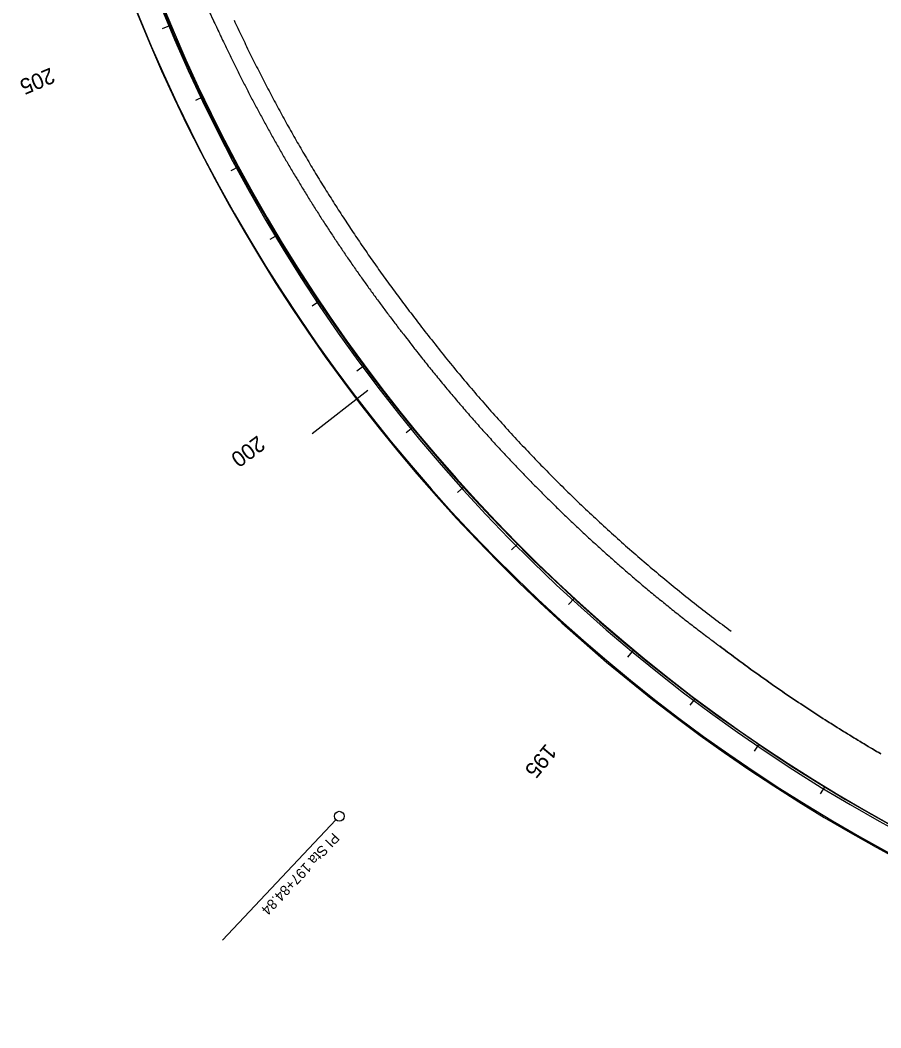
# Model space of a CAD drawing. Extents: x 5180909 to 5237144, y 3695282 to 3720102.
# Drawn here: x 5197859 to 5198956, y 3702771 to 3704056 of the extents above; entities that cross this region are included whole.
import ezdxf

# ---------------------------------------------------------------- set-up
doc = ezdxf.new("R2010")
doc.units = 0
for name, color, linetype in [('Alignment', 7, 'Continuous'), ('Default', 7, 'Continuous'), ('DisFieldPoint', 7, 'Continuous'), ('Draft_0', 7, 'Continuous'), ('dsnEntrancePaved', 7, 'Continuous'), ('dsnShadingGranular', 7, 'Continuous'), ('dsnSidewalkShadingRamp', 7, 'Continuous'), ('dsnStgShadingPropGrdLim', 7, 'Continuous')]:
    doc.layers.add(name, color=color, linetype=linetype)

msp = doc.modelspace()

# ---------------------------------------------------------------- linework, layer by layer
at = {"layer": 'Alignment'}
msp.add_arc((5199969.8, 3704853.2), 2080, 193.5037, 260.0302, dxfattribs=at)
at = {"layer": 'Default'}
msp.add_arc((5199969.8, 3704853.2), 2080, 193.5037, 260.0302, dxfattribs=at)
at = {"layer": 'DisFieldPoint'}
for radius in [2115.5, 2083.5]:
    msp.add_arc((5199970.6, 3704856.4), radius, 191.1921, 260.0343, dxfattribs=at)
at = {"layer": 'Draft_0'}
msp.add_line((5198231.3, 3703528.9), (5198302.4, 3703584.1), dxfattribs=at)
at = {"layer": 'dsnEntrancePaved'}
msp.add_arc((5199969.8, 3704853.2), 2080, 193.5037, 260.0302, dxfattribs=at)
at = {"layer": 'dsnShadingGranular'}
msp.add_line((5198110.1, 3704045.4), (5198110.1, 3704045.4), dxfattribs=at)
msp.add_line((5198110.1, 3704045.4), (5198110.1, 3704045.4), dxfattribs=at)
for centre, radius, start, end in [((5199967.6, 3704851), 2080, 188.6831, 264.8508), ((5199969.8, 3704853.2), 2114, 193.5037, 260.0302)]:
    msp.add_arc(centre, radius, start, end, dxfattribs=at)
for points in [[(5197987, 3704376.2), (5197987, 3704376.2), (5197988.6, 3704370.5), (5197991.8, 3704359.1), (5197996.7, 3704342.1), (5198001.8, 3704325.2), (5198007, 3704308.2), (5198012.4, 3704291.4), (5198017.9, 3704274.6), (5198023.6, 3704257.8), (5198029.4, 3704241.1), (5198035.3, 3704224.4), (5198041.4, 3704207.8), (5198047.7, 3704191.3), (5198054, 3704174.8), (5198060.6, 3704158.4), (5198067.2, 3704142), (5198074, 3704125.7), (5198081, 3704109.5), (5198088, 3704093.3), (5198095.3, 3704077.2), (5198102.6, 3704061.2), (5198107.6, 3704050.7), (5198110.1, 3704045.4), (5198110.1, 3704045.4)], [(5198110.1, 3704045.4), (5198113.3, 3704038.4), (5198116.6, 3704031.4), (5198119.9, 3704024.4), (5198123.3, 3704017.3), (5198126.7, 3704010.3), (5198130.1, 3704003.4), (5198133.5, 3703996.4), (5198137, 3703989.5), (5198140.5, 3703982.5), (5198144, 3703975.6), (5198147.6, 3703968.7), (5198151.1, 3703961.8), (5198154.7, 3703954.9), (5198158.3, 3703948.1), (5198162, 3703941.2), (5198165.7, 3703934.4), (5198169.4, 3703927.6), (5198173.1, 3703920.8), (5198176.8, 3703914), (5198180.6, 3703907.2), (5198184.4, 3703900.4), (5198188.3, 3703893.7), (5198192.1, 3703887), (5198196, 3703880.2), (5198199.9, 3703873.5), (5198203.8, 3703866.9), (5198207.8, 3703860.2), (5198211.8, 3703853.5), (5198215.8, 3703846.9), (5198219.8, 3703840.3), (5198223.8, 3703833.7), (5198227.9, 3703827.1), (5198232, 3703820.5), (5198236.2, 3703814), (5198240.3, 3703807.4), (5198244.5, 3703800.9), (5198248.7, 3703794.4), (5198252.9, 3703787.9), (5198257.2, 3703781.4), (5198261.5, 3703775), (5198265.8, 3703768.5), (5198270.1, 3703762.1), (5198274.4, 3703755.7), (5198278.8, 3703749.3), (5198283.2, 3703743), (5198287.6, 3703736.6), (5198292.1, 3703730.3), (5198296.6, 3703724), (5198301, 3703717.7), (5198305.6, 3703711.4), (5198310.1, 3703705.1), (5198314.7, 3703698.9), (5198319.3, 3703692.7), (5198323.9, 3703686.5), (5198328.5, 3703680.3), (5198333.2, 3703674.1), (5198337.9, 3703667.9), (5198342.6, 3703661.8), (5198347.3, 3703655.7), (5198352, 3703649.7)], [(5198352, 3703649.7), (5198357.6, 3703642.4), (5198363.3, 3703635), (5198369.2, 3703627.6), (5198375, 3703620.2), (5198380.9, 3703612.9), (5198386.8, 3703605.6), (5198392.7, 3703598.4), (5198398.6, 3703591.1), (5198404.7, 3703583.9), (5198410.7, 3703576.7), (5198416.7, 3703569.6), (5198422.8, 3703562.5), (5198428.9, 3703555.4), (5198435.1, 3703548.3), (5198441.3, 3703541.3), (5198447.5, 3703534.3), (5198453.8, 3703527.3), (5198460.1, 3703520.4), (5198466.4, 3703513.5), (5198472.7, 3703506.6), (5198479.1, 3703499.8), (5198485.5, 3703492.9), (5198492, 3703486.1), (5198498.5, 3703479.4), (5198505, 3703472.6), (5198511.5, 3703465.9), (5198518.1, 3703459.3), (5198524.7, 3703452.6), (5198531.3, 3703446), (5198538, 3703439.5), (5198544.6, 3703432.9), (5198551.4, 3703426.4), (5198558.1, 3703419.9), (5198564.9, 3703413.5), (5198571.7, 3703407.1), (5198578.6, 3703400.7), (5198585.4, 3703394.3), (5198592.3, 3703388), (5198599.2, 3703381.7), (5198606.2, 3703375.5), (5198613.2, 3703369.2), (5198620.2, 3703363.1), (5198627.2, 3703356.9), (5198634.3, 3703350.8), (5198641.4, 3703344.7), (5198648.5, 3703338.6), (5198655.6, 3703332.6), (5198662.8, 3703326.6), (5198670, 3703320.7), (5198677.3, 3703314.8), (5198684.5, 3703308.9), (5198691.8, 3703303), (5198699.1, 3703297.2), (5198706.5, 3703291.4), (5198713.8, 3703285.7), (5198721.2, 3703280), (5198728.7, 3703274.3), (5198736.1, 3703268.6), (5198743.6, 3703263.1), (5198751, 3703257.5)], [(5198751, 3703257.5), (5198754.2, 3703255), (5198760.8, 3703250.1), (5198770.7, 3703242.7), (5198780.6, 3703235.4), (5198790.6, 3703228.1), (5198800.7, 3703220.9), (5198810.7, 3703213.7), (5198820.8, 3703206.7), (5198831, 3703199.7), (5198841.2, 3703192.7), (5198851.4, 3703185.8), (5198861.7, 3703179), (5198872.1, 3703172.2), (5198882.4, 3703165.5), (5198892.8, 3703158.9), (5198903.3, 3703152.3), (5198913.8, 3703145.8), (5198924.3, 3703139.3), (5198934.9, 3703133), (5198945.5, 3703126.7), (5198952.6, 3703122.5), (5198956.2, 3703120.4)]]:
    msp.add_open_spline(points, degree=3, dxfattribs=at)
at = {"layer": 'dsnSidewalkShadingRamp'}
for p, q in [((5198051.5, 3704049), (5198040.2, 3704044.3)), ((5198092.4, 3703957.7), (5198082.5, 3703953)), ((5198137.6, 3703868.5), (5198127.9, 3703863.3)), ((5198187, 3703781.6), (5198177.6, 3703776)), ((5198240.6, 3703697.2), (5198231.5, 3703691.1)), ((5198298.2, 3703615.4), (5198288.3, 3703608.1)), ((5198359.6, 3703536.5), (5198351.1, 3703529.6)), ((5198424.7, 3703460.7), (5198416.6, 3703453.3)), ((5198493.4, 3703388), (5198485.6, 3703380.3)), ((5198565.6, 3703318.8), (5198558.1, 3703310.7)), ((5198640.9, 3703253.1), (5198633.1, 3703243.6)), ((5198719.4, 3703191), (5198712.7, 3703182.3)), ((5198800.7, 3703132.9), (5198794.5, 3703123.8)), ((5198884.7, 3703078.7), (5198879, 3703069.3)), ((5198261.6, 3703036.3), (5198117.3, 3702882.8))]:
    msp.add_line(p, q, dxfattribs=at)
msp.add_circle((5198265.9, 3703040.9), 6.25, dxfattribs=at)
for points in [[(5197987, 3704376.2), (5197987, 3704376.2), (5197988.6, 3704370.5), (5197991.8, 3704359.1), (5197996.7, 3704342.1), (5198001.8, 3704325.2), (5198007, 3704308.2), (5198012.4, 3704291.4), (5198017.9, 3704274.6), (5198023.6, 3704257.8), (5198029.4, 3704241.1), (5198035.3, 3704224.4), (5198041.4, 3704207.8), (5198047.7, 3704191.3), (5198054, 3704174.8), (5198060.6, 3704158.4), (5198067.2, 3704142), (5198074, 3704125.7), (5198081, 3704109.5), (5198088, 3704093.3), (5198095.3, 3704077.2), (5198102.6, 3704061.2), (5198107.6, 3704050.7), (5198110.1, 3704045.4), (5198110.1, 3704045.4)], [(5197987, 3704376.2), (5197987, 3704376.2), (5197988.6, 3704370.5), (5197991.8, 3704359.1), (5197996.7, 3704342.1), (5198001.8, 3704325.2), (5198007, 3704308.2), (5198012.4, 3704291.4), (5198017.9, 3704274.6), (5198023.6, 3704257.8), (5198029.4, 3704241.1), (5198035.3, 3704224.4), (5198041.4, 3704207.8), (5198047.7, 3704191.3), (5198054, 3704174.8), (5198060.6, 3704158.4), (5198067.2, 3704142), (5198074, 3704125.7), (5198081, 3704109.5), (5198088, 3704093.3), (5198095.3, 3704077.2), (5198102.6, 3704061.2), (5198107.6, 3704050.7), (5198110.1, 3704045.4), (5198110.1, 3704045.4)], [(5198110.1, 3704045.4), (5198113.3, 3704038.4), (5198116.6, 3704031.4), (5198119.9, 3704024.4), (5198123.3, 3704017.3), (5198126.7, 3704010.3), (5198130.1, 3704003.4), (5198133.5, 3703996.4), (5198137, 3703989.5), (5198140.5, 3703982.5), (5198144, 3703975.6), (5198147.6, 3703968.7), (5198151.1, 3703961.8), (5198154.7, 3703954.9), (5198158.3, 3703948.1), (5198162, 3703941.2), (5198165.7, 3703934.4), (5198169.4, 3703927.6), (5198173.1, 3703920.8), (5198176.8, 3703914), (5198180.6, 3703907.2), (5198184.4, 3703900.4), (5198188.3, 3703893.7), (5198192.1, 3703887), (5198196, 3703880.2), (5198199.9, 3703873.5), (5198203.8, 3703866.9), (5198207.8, 3703860.2), (5198211.8, 3703853.5), (5198215.8, 3703846.9), (5198219.8, 3703840.3), (5198223.8, 3703833.7), (5198227.9, 3703827.1), (5198232, 3703820.5), (5198236.2, 3703814), (5198240.3, 3703807.4), (5198244.5, 3703800.9), (5198248.7, 3703794.4), (5198252.9, 3703787.9), (5198257.2, 3703781.4), (5198261.5, 3703775), (5198265.8, 3703768.5), (5198270.1, 3703762.1), (5198274.4, 3703755.7), (5198278.8, 3703749.3), (5198283.2, 3703743), (5198287.6, 3703736.6), (5198292.1, 3703730.3), (5198296.6, 3703724), (5198301, 3703717.7), (5198305.6, 3703711.4), (5198310.1, 3703705.1), (5198314.7, 3703698.9), (5198319.3, 3703692.7), (5198323.9, 3703686.5), (5198328.5, 3703680.3), (5198333.2, 3703674.1), (5198337.9, 3703667.9), (5198342.6, 3703661.8), (5198347.3, 3703655.7), (5198352, 3703649.7)], [(5198110.1, 3704045.4), (5198113.3, 3704038.4), (5198116.6, 3704031.4), (5198119.9, 3704024.4), (5198123.3, 3704017.3), (5198126.7, 3704010.3), (5198130.1, 3704003.4), (5198133.5, 3703996.4), (5198137, 3703989.5), (5198140.5, 3703982.5), (5198144, 3703975.6), (5198147.6, 3703968.7), (5198151.1, 3703961.8), (5198154.7, 3703954.9), (5198158.3, 3703948.1), (5198162, 3703941.2), (5198165.7, 3703934.4), (5198169.4, 3703927.6), (5198173.1, 3703920.8), (5198176.8, 3703914), (5198180.6, 3703907.2), (5198184.4, 3703900.4), (5198188.3, 3703893.7), (5198192.1, 3703887), (5198196, 3703880.2), (5198199.9, 3703873.5), (5198203.8, 3703866.9), (5198207.8, 3703860.2), (5198211.8, 3703853.5), (5198215.8, 3703846.9), (5198219.8, 3703840.3), (5198223.8, 3703833.7), (5198227.9, 3703827.1), (5198232, 3703820.5), (5198236.2, 3703814), (5198240.3, 3703807.4), (5198244.5, 3703800.9), (5198248.7, 3703794.4), (5198252.9, 3703787.9), (5198257.2, 3703781.4), (5198261.5, 3703775), (5198265.8, 3703768.5), (5198270.1, 3703762.1), (5198274.4, 3703755.7), (5198278.8, 3703749.3), (5198283.2, 3703743), (5198287.6, 3703736.6), (5198292.1, 3703730.3), (5198296.6, 3703724), (5198301, 3703717.7), (5198305.6, 3703711.4), (5198310.1, 3703705.1), (5198314.7, 3703698.9), (5198319.3, 3703692.7), (5198323.9, 3703686.5), (5198328.5, 3703680.3), (5198333.2, 3703674.1), (5198337.9, 3703667.9), (5198342.6, 3703661.8), (5198347.3, 3703655.7), (5198352, 3703649.7)]]:
    msp.add_open_spline(points, degree=3, dxfattribs=at)
at = {"layer": 'dsnStgShadingPropGrdLim'}
for points in [[(5198131.8, 3704055.5), (5198135.1, 3704048.6), (5198141.6, 3704034.7), (5198151.6, 3704014), (5198161.9, 3703993.4), (5198172.4, 3703972.9), (5198183.1, 3703952.5), (5198194.1, 3703932.3), (5198205.3, 3703912.2), (5198216.7, 3703892.3), (5198228.4, 3703872.5), (5198240.2, 3703852.8), (5198252.3, 3703833.3), (5198264.7, 3703813.9), (5198277.2, 3703794.6), (5198289.9, 3703775.6), (5198302.9, 3703756.6), (5198316.1, 3703737.8), (5198329.5, 3703719.2), (5198343.1, 3703700.8), (5198356.9, 3703682.5), (5198366.3, 3703670.4), (5198370.9, 3703664.4)], [(5198370.9, 3703664.4), (5198376.6, 3703657.1), (5198387.9, 3703642.4), (5198405.3, 3703620.7), (5198423, 3703599.3), (5198441, 3703578.1), (5198459.2, 3703557.2), (5198477.8, 3703536.5), (5198496.6, 3703516.1), (5198515.7, 3703496), (5198535.1, 3703476.1), (5198554.7, 3703456.5), (5198574.7, 3703437.2), (5198594.8, 3703418.2), (5198615.3, 3703399.5), (5198636, 3703381.1), (5198656.9, 3703362.9), (5198678.1, 3703345.1), (5198699.6, 3703327.5), (5198721.2, 3703310.3), (5198743.1, 3703293.3), (5198757.9, 3703282.3), (5198765.3, 3703276.8)], [(5198352, 3703649.7), (5198357.6, 3703642.4), (5198363.3, 3703635), (5198369.2, 3703627.6), (5198375, 3703620.2), (5198380.9, 3703612.9), (5198386.8, 3703605.6), (5198392.7, 3703598.4), (5198398.6, 3703591.1), (5198404.7, 3703583.9), (5198410.7, 3703576.7), (5198416.7, 3703569.6), (5198422.8, 3703562.5), (5198428.9, 3703555.4), (5198435.1, 3703548.3), (5198441.3, 3703541.3), (5198447.5, 3703534.3), (5198453.8, 3703527.3), (5198460.1, 3703520.4), (5198466.4, 3703513.5), (5198472.7, 3703506.6), (5198479.1, 3703499.8), (5198485.5, 3703492.9), (5198492, 3703486.1), (5198498.5, 3703479.4), (5198505, 3703472.6), (5198511.5, 3703465.9), (5198518.1, 3703459.3), (5198524.7, 3703452.6), (5198531.3, 3703446), (5198538, 3703439.5), (5198544.6, 3703432.9), (5198551.4, 3703426.4), (5198558.1, 3703419.9), (5198564.9, 3703413.5), (5198571.7, 3703407.1), (5198578.6, 3703400.7), (5198585.4, 3703394.3), (5198592.3, 3703388), (5198599.2, 3703381.7), (5198606.2, 3703375.5), (5198613.2, 3703369.2), (5198620.2, 3703363.1), (5198627.2, 3703356.9), (5198634.3, 3703350.8), (5198641.4, 3703344.7), (5198648.5, 3703338.6), (5198655.6, 3703332.6), (5198662.8, 3703326.6), (5198670, 3703320.7), (5198677.3, 3703314.8), (5198684.5, 3703308.9), (5198691.8, 3703303), (5198699.1, 3703297.2), (5198706.5, 3703291.4), (5198713.8, 3703285.7), (5198721.2, 3703280), (5198728.7, 3703274.3), (5198736.1, 3703268.6), (5198743.6, 3703263.1), (5198751, 3703257.5)], [(5198352, 3703649.7), (5198357.6, 3703642.4), (5198363.3, 3703635), (5198369.2, 3703627.6), (5198375, 3703620.2), (5198380.9, 3703612.9), (5198386.8, 3703605.6), (5198392.7, 3703598.4), (5198398.6, 3703591.1), (5198404.7, 3703583.9), (5198410.7, 3703576.7), (5198416.7, 3703569.6), (5198422.8, 3703562.5), (5198428.9, 3703555.4), (5198435.1, 3703548.3), (5198441.3, 3703541.3), (5198447.5, 3703534.3), (5198453.8, 3703527.3), (5198460.1, 3703520.4), (5198466.4, 3703513.5), (5198472.7, 3703506.6), (5198479.1, 3703499.8), (5198485.5, 3703492.9), (5198492, 3703486.1), (5198498.5, 3703479.4), (5198505, 3703472.6), (5198511.5, 3703465.9), (5198518.1, 3703459.3), (5198524.7, 3703452.6), (5198531.3, 3703446), (5198538, 3703439.5), (5198544.6, 3703432.9), (5198551.4, 3703426.4), (5198558.1, 3703419.9), (5198564.9, 3703413.5), (5198571.7, 3703407.1), (5198578.6, 3703400.7), (5198585.4, 3703394.3), (5198592.3, 3703388), (5198599.2, 3703381.7), (5198606.2, 3703375.5), (5198613.2, 3703369.2), (5198620.2, 3703363.1), (5198627.2, 3703356.9), (5198634.3, 3703350.8), (5198641.4, 3703344.7), (5198648.5, 3703338.6), (5198655.6, 3703332.6), (5198662.8, 3703326.6), (5198670, 3703320.7), (5198677.3, 3703314.8), (5198684.5, 3703308.9), (5198691.8, 3703303), (5198699.1, 3703297.2), (5198706.5, 3703291.4), (5198713.8, 3703285.7), (5198721.2, 3703280), (5198728.7, 3703274.3), (5198736.1, 3703268.6), (5198743.6, 3703263.1), (5198751, 3703257.5)], [(5198956.2, 3703120.4), (5198952.6, 3703122.5), (5198945.5, 3703126.7), (5198934.9, 3703133), (5198924.3, 3703139.3), (5198913.8, 3703145.8), (5198903.3, 3703152.3), (5198892.8, 3703158.9), (5198882.4, 3703165.5), (5198872.1, 3703172.2), (5198861.7, 3703179), (5198851.4, 3703185.8), (5198841.2, 3703192.7), (5198831, 3703199.7), (5198820.8, 3703206.7), (5198810.7, 3703213.7), (5198800.7, 3703220.9), (5198790.6, 3703228.1), (5198780.6, 3703235.4), (5198770.7, 3703242.7), (5198760.8, 3703250.1), (5198754.2, 3703255), (5198751, 3703257.5)]]:
    msp.add_open_spline(points, degree=3, dxfattribs=at)

# ---------------------------------------------------------------- texts
at = {"layer": 'dsnSidewalkShadingRamp'}
for s, height, rotation, p in [('205', 20, 202.7468, (5197898, 3703995.5)), ('200', 20, 216.5198, (5198161.8, 3703526.9)), ('195', 20, 230.2928, (5198529.6, 3703134.6)), ('PI Sta 197+84.84', 13, 226.7669, (5198258, 3703020.8))]:
    msp.add_text(s, height=height, rotation=rotation, dxfattribs=at).set_placement(p)

doc.saveas('drawing.dxf')
